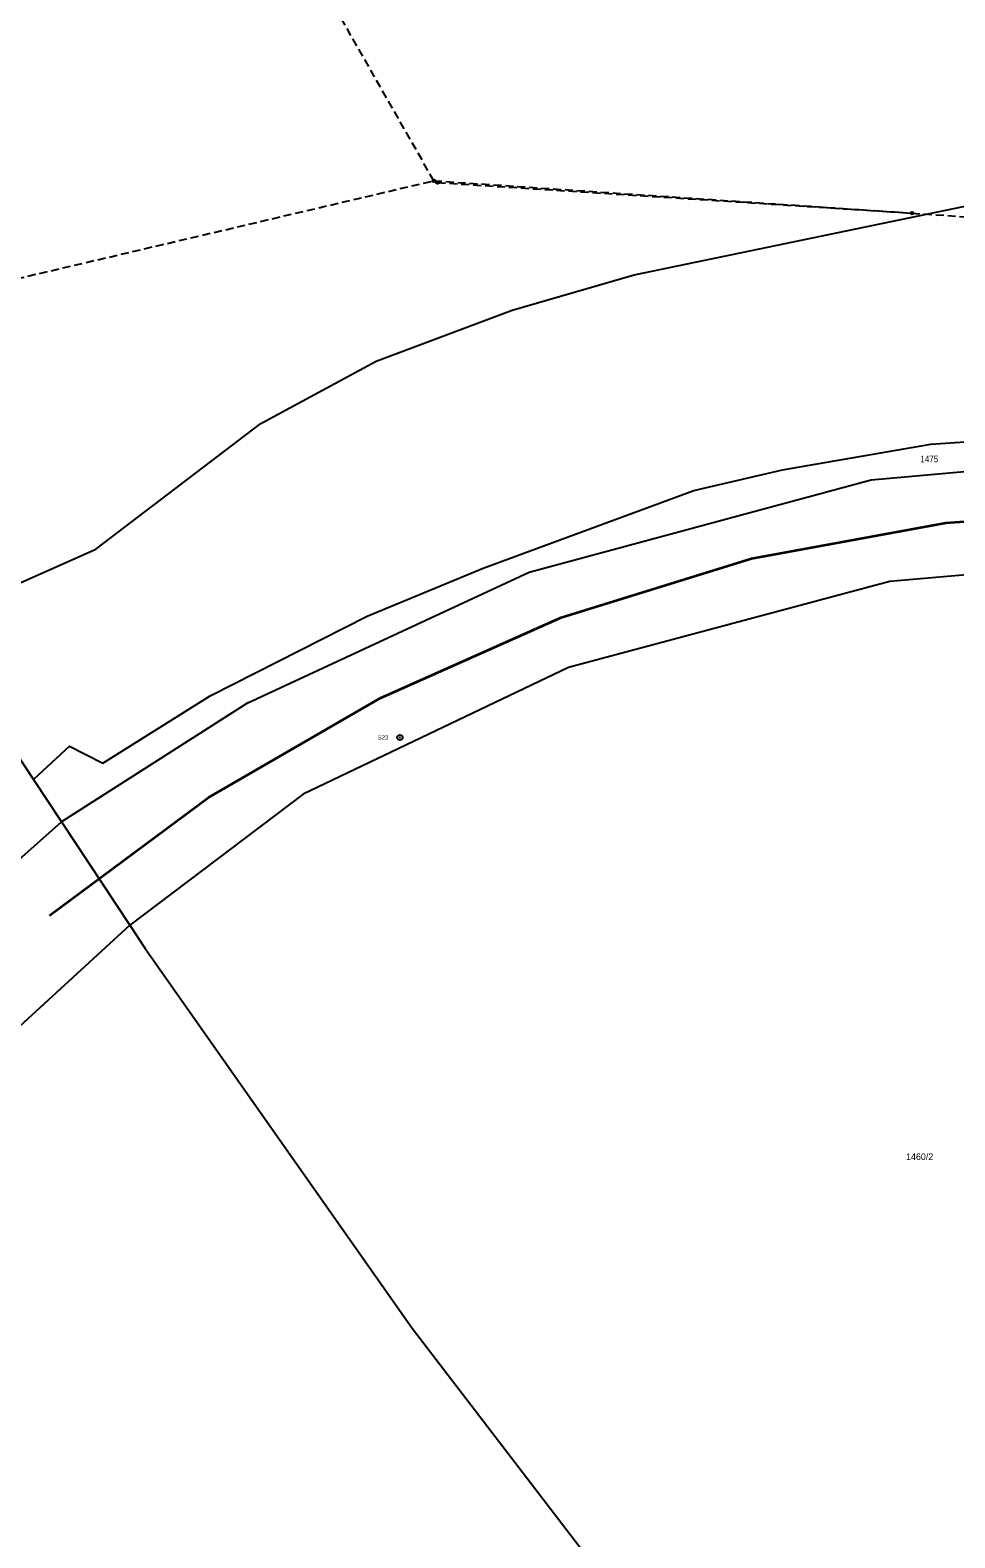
# Model space of a CAD drawing. Extents: x -873052 to -871788, y -1075760 to -1074911.
# Drawn here: x -872101.8 to -871997.3, y -1075252.5 to -1075082.2 of the extents above; entities that cross this region are included whole.
import ezdxf
from ezdxf.enums import TextEntityAlignment as Align

# ---------------------------------------------------------------- set-up
doc = ezdxf.new("R2010")
doc.units = 0
doc.header["$LTSCALE"] = 0.3
doc.linetypes.add('MEDIUM_DASHED', pattern=[4.5, 3, -1.5])
for name, color, linetype, lineweight in [('1', 7, 'Continuous', 25), ('10', 7, 'Continuous', 35), ('12', 7, 'MEDIUM_DASHED', 25), ('13', 7, 'Continuous', 25), ('24', 7, 'Continuous', 25), ('26', 7, 'Continuous', 25)]:
    doc.layers.add(name, color=color, linetype=linetype, lineweight=lineweight)
doc.layers.add('17', color=7, linetype='Continuous')
doc.layers.add('18', color=7, linetype='Continuous')

msp = doc.modelspace()

# ---------------------------------------------------------------- linework, layer by layer
at = {"layer": '1'}
for p, q in [((-872077.16, -1075158.13), (-872098.2, -1075171.61)), ((-872097.33, -1075163.03), (-872101.38, -1075166.81)), ((-872070.91, -1075168.48), (-872090.5, -1075183.25))]:
    msp.add_line(p, q, dxfattribs=at)
for points in [[(-872077.16, -1075158.13), (-872045.37, -1075143.38), (-872006.74, -1075132.95), (-871959.96, -1075128.78), (-871912.71, -1075138.77)], [(-872016.77, -1075131.83), (-872000, -1075128.92), (-871983.47, -1075127.8), (-871967.52, -1075127.44), (-871948.24, -1075128.23)], [(-872063.68, -1075148.34), (-872050.57, -1075142.92), (-872026.79, -1075134.16), (-872016.77, -1075131.83)], [(-871973.44, -1075141.74), (-872004.63, -1075144.44), (-872040.93, -1075154.15), (-872070.91, -1075168.48)], [(-872097.33, -1075163.03), (-872093.54, -1075164.98), (-872081.42, -1075157.36), (-872063.68, -1075148.34)], [(-872175.82, -1075260.09), (-872152.8, -1075227.87), (-872120.8, -1075191.65), (-872098.2, -1075171.61)], [(-872090.5, -1075183.25), (-872110.82, -1075201.89), (-872126.18, -1075218.42), (-872139.94, -1075235.75), (-872164.9, -1075268.87), (-872190.66, -1075303.41), (-872220.26, -1075342), (-872225.14, -1075345.71), (-872230.99, -1075353.55), (-872230.06, -1075355.76), (-872245.23, -1075376.67), (-872277.88, -1075420.38), (-872293.14, -1075441), (-872310.02, -1075462.12), (-872328.57, -1075481.4), (-872352.74, -1075501.12), (-872369.24, -1075513.31), (-872390.58, -1075524.1), (-872416.47, -1075534.8), (-872442.75, -1075542.81), (-872455.78, -1075544.66), (-872509.66, -1075552.26)]]:
    msp.add_lwpolyline(points, dxfattribs=at)
at = {"layer": '10'}
msp.add_lwpolyline([(-872099.58, -1075182.16), (-872081.61, -1075168.85), (-872062.2, -1075157.62), (-872041.76, -1075148.51), (-872020.26, -1075141.84), (-871998.31, -1075137.82), (-871975.9, -1075136.21), (-871953.52, -1075137.1), (-871931.29, -1075140.4), (-871909.71, -1075146.24)], dxfattribs=at)
at = {"layer": '12'}
for p, q in [((-872056.15, -1075099.17), (-872002.14, -1075102.83)), ((-872055.75, -1075099.37), (-872002.14, -1075102.83)), ((-872002.14, -1075102.83), (-871927.7, -1075107.92)), ((-872002.14, -1075102.83), (-872000.53, -1075102.94))]:
    msp.add_line(p, q, dxfattribs=at)
msp.add_lwpolyline([(-872121.72, -1075114.58), (-872056.15, -1075099.17), (-872092.6, -1075035.3), (-872128.23, -1074972.65), (-872162.98, -1074911.84)], dxfattribs=at)
at = {"layer": '13'}
for p, q in [((-872033.51, -1075109.78), (-871976.71, -1075098)), ((-872110.79, -1075148.09), (-872094.35, -1075140.79)), ((-872113.09, -1075149.11), (-872101.38, -1075166.81)), ((-872101.38, -1075166.81), (-872098.2, -1075171.61)), ((-872098.2, -1075171.61), (-872090.5, -1075183.25))]:
    msp.add_line(p, q, dxfattribs=at)
for points in [[(-872094.35, -1075140.79), (-872075.71, -1075126.6), (-872062.66, -1075119.57), (-872047.32, -1075113.79), (-872033.51, -1075109.78)], [(-872090.5, -1075183.25), (-872088.76, -1075185.89), (-872058.62, -1075228.79), (-872029.97, -1075266.16), (-872020.73, -1075284.28)]]:
    msp.add_lwpolyline(points, dxfattribs=at)
at = {"layer": '24'}
for radius in [0.3005, 0.00951]:
    msp.add_circle((-872059.9795, -1075162.0695), radius, dxfattribs=at)
at = {"layer": '26'}
for centre, radius in [((-872056.1495, -1075099.1695), 0.1505), ((-872056.1495, -1075099.1695), 0.0905), ((-872056.1495, -1075099.1695), 0.0455), ((-872055.7495, -1075099.3695), 0.1505), ((-872055.7495, -1075099.3695), 0.0905), ((-872055.7495, -1075099.3695), 0.0455), ((-872002.1395, -1075102.8295), 0.1505), ((-872002.1395, -1075102.8295), 0.0905), ((-872002.1395, -1075102.8295), 0.0455)]:
    msp.add_circle(centre, radius, dxfattribs=at)

# ---------------------------------------------------------------- texts
at = {"layer": '17', "width": 0.9}
msp.add_text('523', height=0.51, dxfattribs=at).set_placement((-872061.28, -1075162.324), align=Align.RIGHT)
at = {"layer": '18', "width": 0.9}
msp.add_text('1475', height=0.75, dxfattribs=at).set_placement((-872000.1795, -1075130.98), align=Align.CENTER)
at = {"layer": '18'}
msp.add_text('1460/2', height=0.75, dxfattribs=at).set_placement((-872002.8, -1075209.8))

doc.saveas('drawing.dxf')
